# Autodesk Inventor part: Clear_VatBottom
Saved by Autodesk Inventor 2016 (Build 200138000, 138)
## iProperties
Created: 2015-11
Part Number: Clear_VatBottom
Material: Generic
Document SubType Name: Modeling
Designer: John
Density: 1 g/cm^3
Appearance: Default
Author: John
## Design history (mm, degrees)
feature "Base1"
body "Solid1"
